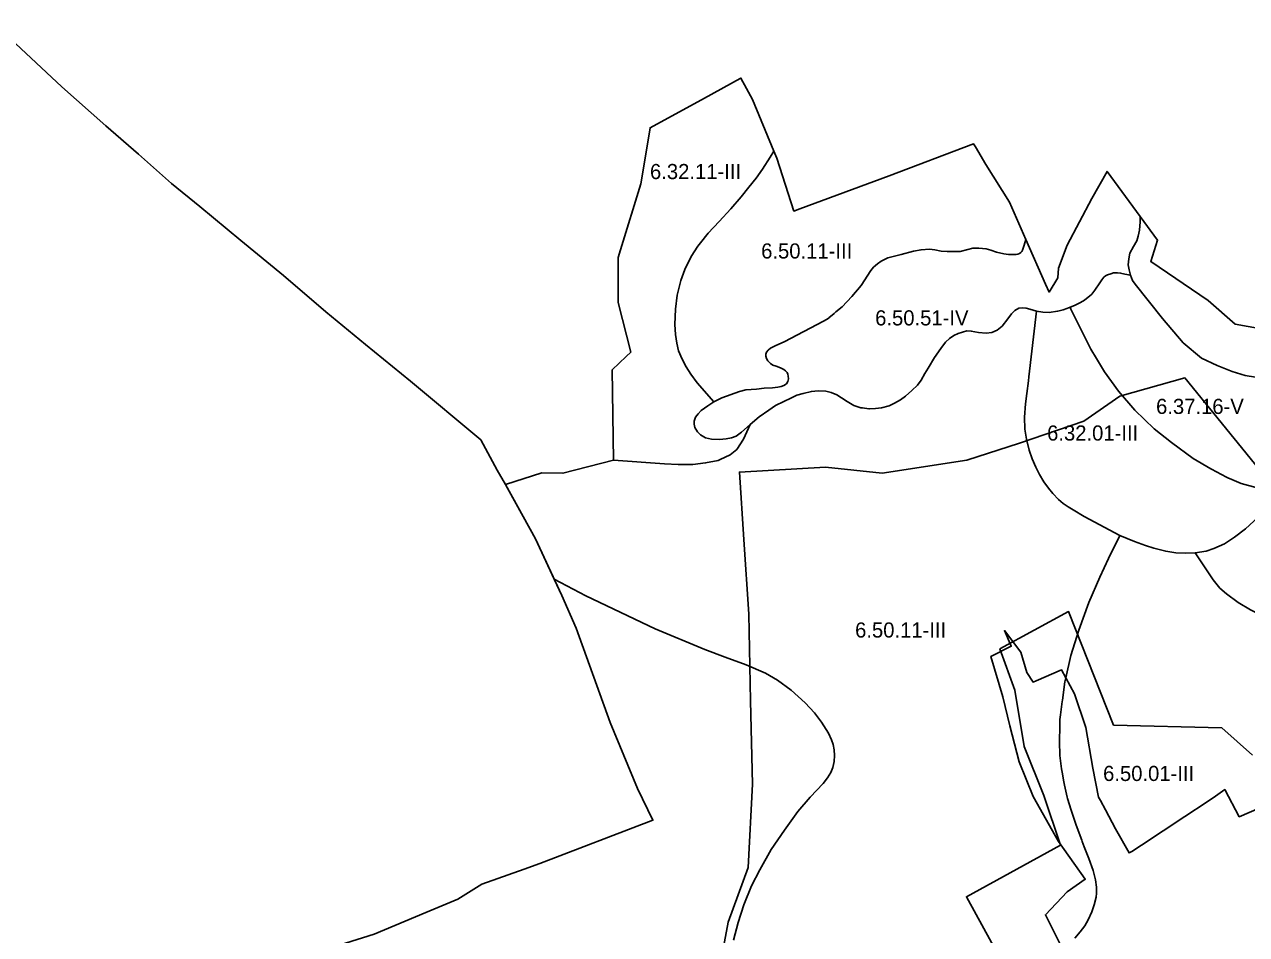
# Model space of a CAD drawing. Extents: x -555156 to -540209, y -1046851 to -1035695.
# Drawn here: x -543396 to -542589, y -1037595 to -1036993 of the extents above; entities that cross this region are included whole.
import ezdxf

# ---------------------------------------------------------------- set-up
doc = ezdxf.new("R2010")
doc.units = 0
for name, color, linetype in [('Vrstva 12', 7, 'Continuous'), ('Vrstva 27', 7, 'Continuous'), ('Vrstva 28', 7, 'Continuous'), ('Vrstva 29', 7, 'Continuous')]:
    doc.layers.add(name, color=color, linetype=linetype)

msp = doc.modelspace()

# ---------------------------------------------------------------- linework, layer by layer
at = {"layer": 'Vrstva 12'}
msp.add_lwpolyline([(-542515.82, -1037483.08), (-542593.49, -1037516.73), (-542603.09, -1037498.84), (-542609.16, -1037503.08), (-542614.79, -1037506.8), (-542629.42, -1037516.55), (-542658.02, -1037535.52), (-542664.44, -1037539.79), (-542666.3, -1037540.7), (-542675.35, -1037524.75), (-542681.98, -1037512.26), (-542685.31, -1037505.99), (-542686.48, -1037503.78), (-542690.35, -1037484.73), (-542694.88, -1037457.81), (-542702.41, -1037435.49), (-542711.03, -1037419.55), (-542727.68, -1037426.79), (-542729.77, -1037427.7), (-542733.8, -1037421.3), (-542737.96, -1037407.96), (-542748.71, -1037393.72), (-542744.2, -1037404.08), (-542757.6, -1037410.72), (-542749.7, -1037437.38), (-542745.23, -1037456.61), (-542739, -1037480.36), (-542729.66, -1037503.33), (-542713.06, -1037533.06), (-542695.314088, -1037558.028085), (-542707.15, -1037566.44), (-542721.64, -1037581.51), (-542703.165119, -1037618.59666)], dxfattribs=at)
at = {"layer": 'Vrstva 28'}
for points in [[(-543415.88, -1036992.99), (-543371.66, -1037034.13), (-543342.6, -1037060.06), (-543320.91, -1037078.65), (-543299.25, -1037098.09), (-543280.46, -1037113.29), (-543253.43, -1037135.74), (-543225.14, -1037158.87), (-543197.14, -1037182.9), (-543170.98, -1037204.56), (-543141.16, -1037228.74), (-543094.74, -1037267.62), (-543083.9, -1037287.54), (-543078.48, -1037297.12), (-543077.17, -1037299.48), (-543058.55, -1037332.92), (-543041.26, -1037370.55), (-543031.79, -1037392.1), (-543009.21, -1037454.54), (-542991.19, -1037498.05), (-542980.98, -1037519.01), (-543055.79, -1037547.74), (-543066.03, -1037551.41), (-543094.01, -1037561.29), (-543110.06, -1037571.25), (-543131.14, -1037580.09), (-543165.36, -1037594.45), (-543203.18, -1037606.26)], [(-542901.06, -1037076.86), (-542915.2, -1037042.72), (-542919.13, -1037035.39), (-542922.83, -1037028.49), (-542923.39, -1037028.8), (-542946.9, -1037041.67), (-542982.89, -1037061.33), (-542983.82, -1037066.88), (-542989.08, -1037098.45), (-543002.42, -1037141.91), (-543004.02, -1037147.14), (-543003.94, -1037176.88), (-542995.65, -1037209.54), (-542998.77, -1037212.51), (-543008.04, -1037221.32), (-543007.13, -1037280.98)], [(-542745.42, -1037110.47), (-542760.97, -1037085.53), (-542767.92, -1037073.99), (-542769.18, -1037071.9), (-542824.86, -1037092.98), (-542883.9, -1037114.88), (-542887.81, -1037116.35), (-542899.14, -1037081.5), (-542901.06, -1037076.86)], [(-542901.06, -1037076.86), (-542903.53, -1037080.78), (-542908.55, -1037088.58), (-542912.86, -1037094.71), (-542917.6, -1037100.56), (-542922.75, -1037106.97), (-542929.57, -1037114.91), (-542937.27, -1037123.3), (-542944.51, -1037130.96), (-542949.5, -1037137.28), (-542951.33, -1037139.6), (-542955.65, -1037146.43), (-542959.97, -1037155.06), (-542962.61, -1037162.17), (-542964.98, -1037171.92), (-542966.09, -1037181.11), (-542966.59, -1037191.25), (-542966.2, -1037197.93), (-542965.32, -1037203.67), (-542964.13, -1037208.76), (-542961.66, -1037214.25), (-542958.96, -1037219.43), (-542956.01, -1037224.12), (-542951.83, -1037229.9), (-542940.76, -1037242.4)], [(-542658.9, -1037119.98), (-542680.89, -1037090.17), (-542691.04, -1037108.02), (-542707.24, -1037138.98), (-542713.05, -1037154.16), (-542713.34, -1037160.45), (-542719.18, -1037169.92), (-542721.53, -1037164.59), (-542734.51, -1037135.2)], [(-542734.51, -1037135.2), (-542745.42, -1037110.47)], [(-542666.33, -1037155.28), (-542666.89, -1037151.86), (-542666.57, -1037148.03), (-542665.77, -1037144.29), (-542663.39, -1037139.68), (-542661.27, -1037135.97), (-542660.31, -1037132.87), (-542659.36, -1037128.97), (-542659.04, -1037123.48), (-542658.9, -1037119.98)], [(-542570.54, -1037195.82), (-542596.19, -1037191.22), (-542614.09, -1037175.43), (-542651.98, -1037149.77), (-542647.45, -1037135.49), (-542658.9, -1037119.98)], [(-542734.51, -1037135.2), (-542735.58, -1037138.98), (-542736.71, -1037142.23), (-542737.21, -1037143.17), (-542737.86, -1037143.84), (-542738.84, -1037144.42), (-542739.75, -1037144.81), (-542740.87, -1037145.07), (-542742.22, -1037145.17), (-542745.97, -1037145), (-542749.08, -1037144.68), (-542754.01, -1037143.56), (-542757.59, -1037142.21), (-542760.77, -1037141.41), (-542765.63, -1037140.86), (-542769.53, -1037140.86), (-542772.79, -1037141.73), (-542777.96, -1037143), (-542781.46, -1037143.16), (-542786.55, -1037143.16), (-542790.45, -1037142.77), (-542794.75, -1037141.89), (-542798.31, -1037141.65), (-542803.8, -1037141.89), (-542808.73, -1037142.92), (-542817.01, -1037144.99), (-542825.76, -1037147.3), (-542830.13, -1037149.37), (-542832.68, -1037151.2), (-542835.15, -1037153.43), (-542836.93, -1037155.65), (-542843.37, -1037165.6), (-542849.58, -1037172.85), (-542856.02, -1037179.77), (-542860.05, -1037182.96), (-542861.35, -1037183.99), (-542864.69, -1037187.02), (-542864.82, -1037187.1), (-542868.22, -1037189.18), (-542894.33, -1037202.83), (-542899.88, -1037205.19), (-542903.29, -1037207.01), (-542904.97, -1037208.33), (-542905.97, -1037209.69), (-542906.38, -1037210.97), (-542906.38, -1037212.38), (-542905.97, -1037213.79), (-542905.05, -1037215.29), (-542903.32, -1037217.23), (-542901.68, -1037218.19), (-542899.64, -1037218.87), (-542897.91, -1037219.55), (-542896.27, -1037220.23), (-542894.55, -1037221.19), (-542893.36, -1037222.01), (-542892.36, -1037223.06), (-542891.86, -1037224.28), (-542891.54, -1037225.56), (-542891.41, -1037227.29), (-542891.77, -1037229.11), (-542892.77, -1037230.47), (-542894.55, -1037231.61), (-542896.18, -1037232.29), (-542898.55, -1037232.74), (-542902.08, -1037233.22), (-542907.57, -1037233.54), (-542912.66, -1037234.09), (-542919.66, -1037234.57), (-542923.86, -1037235.55), (-542935.43, -1037239.77), (-542940.76, -1037242.4)], [(-542665.46, -1037158.78), (-542666.33, -1037155.28)], [(-542705.37, -1037179.98), (-542702.37, -1037178.75), (-542698.5, -1037176.83), (-542695.9, -1037175.33), (-542693.31, -1037173.37), (-542692.55, -1037172.65), (-542691.04, -1037171.24), (-542689.04, -1037168.6), (-542685.76, -1037163.91), (-542684.4, -1037161.82), (-542682.95, -1037160.14), (-542681.9, -1037159.18), (-542680.66, -1037158.48), (-542678.43, -1037157.76), (-542676.52, -1037157.28), (-542673.98, -1037157.12), (-542671.91, -1037157.36), (-542669.04, -1037158), (-542665.46, -1037158.78)], [(-542665.46, -1037158.78), (-542664.02, -1037162.2), (-542662.37, -1037164.63), (-542644.27, -1037187.35), (-542630.63, -1037203.37), (-542618.51, -1037213.54), (-542608.21, -1037218.42), (-542598.18, -1037222.32), (-542589.69, -1037224.96)], [(-542916.66, -1037257.37), (-542910.77, -1037252.43), (-542904.49, -1037248.01), (-542900.11, -1037244.9), (-542894.54, -1037242.28), (-542889.93, -1037240.05), (-542885.95, -1037238.06), (-542881.65, -1037236.86), (-542876.24, -1037235.59), (-542871.71, -1037235.19), (-542866.69, -1037235.43), (-542863.19, -1037236.23), (-542859.53, -1037237.74), (-542856.46, -1037239.84), (-542852.65, -1037242.31), (-542848.27, -1037244.78), (-542843.65, -1037246.37), (-542842.52, -1037246.52), (-542838.32, -1037247.09), (-542837.93, -1037247.08), (-542833.95, -1037246.93), (-542829.89, -1037246.37), (-542824.96, -1037245.02), (-542821.3, -1037243.27), (-542817.48, -1037241.2), (-542814.06, -1037238.65), (-542809.84, -1037234.99), (-542806.26, -1037231.41), (-542803.79, -1037228.06), (-542801.33, -1037223.84), (-542799.08, -1037220.2), (-542794.87, -1037213.19), (-542790.65, -1037207.14), (-542787.55, -1037202.92), (-542785.08, -1037200.53), (-542782.14, -1037198.7), (-542779.19, -1037197.27), (-542776.41, -1037196.31), (-542773.46, -1037195.6), (-542770.6, -1037195.68), (-542765.83, -1037196.63), (-542760.73, -1037197.03), (-542757.11, -1037196.6), (-542753.53, -1037195.16), (-542750.27, -1037192.54), (-542746.45, -1037187.68), (-542743.98, -1037184.34), (-542741.92, -1037182.03), (-542739.29, -1037180.59), (-542736.58, -1037180.28), (-542734.28, -1037180.59), (-542731.83, -1037181.17), (-542727.47, -1037182.53)], [(-542727.47, -1037182.53), (-542723.24, -1037183.21), (-542719.19, -1037183.35), (-542713.6, -1037182.62), (-542712.5, -1037182.36), (-542709.96, -1037181.76), (-542707.42, -1037180.78), (-542705.37, -1037179.98)], [(-542705.37, -1037179.98), (-542704.76, -1037181.21)], [(-542672.35, -1037330.88), (-542695.93, -1037318.26), (-542703.24, -1037313.95), (-542706.56, -1037311.93), (-542709.96, -1037309.58), (-542712.87, -1037307.07), (-542716.76, -1037303.02), (-542719.51, -1037299.62), (-542722.66, -1037295.24), (-542725.5, -1037290.55), (-542727.93, -1037285.61), (-542730.27, -1037280.1), (-542732.3, -1037274.43), (-542734.16, -1037267.06), (-542735.15, -1037260.48), (-542735.43, -1037252.54), (-542734.72, -1037243.76), (-542733.91, -1037236.98), (-542732.9, -1037228.58), (-542732.6, -1037226.04), (-542727.47, -1037182.53)], [(-542704.76, -1037181.21), (-542691.64, -1037207.59), (-542691.59, -1037207.69), (-542687.89, -1037213.86), (-542682.67, -1037222.57), (-542673.25, -1037235.47), (-542662.59, -1037247.87), (-542649.7, -1037260.27), (-542638.3, -1037269.44), (-542623.92, -1037279.86), (-542612.27, -1037286.81), (-542611.77, -1037287.07), (-542601.86, -1037292.26), (-542601.09, -1037292.6), (-542598.32, -1037293.8), (-542592.19, -1037296.48), (-542581.78, -1037299.21), (-542563.36, -1037300.23)], [(-542589.69, -1037224.96), (-542582.73, -1037226.08)], [(-542940.76, -1037242.4), (-542944.82, -1037245.19), (-542949.04, -1037248.29), (-542951.11, -1037250.44), (-542952.86, -1037252.59), (-542953.73, -1037255.3), (-542953.81, -1037257.13), (-542953.25, -1037259.44), (-542951.66, -1037262.3), (-542949.67, -1037264.29), (-542946.17, -1037266.28), (-542942.35, -1037267.16)], [(-542916.66, -1037257.37), (-542921.16, -1037267.12), (-542925.48, -1037273.95), (-542930.08, -1037277.57), (-542936.49, -1037280.55), (-542937.87, -1037281.19), (-542946.23, -1037282.87), (-542954.58, -1037283.98), (-542964.33, -1037283.84), (-542973.38, -1037283.42), (-543007.13, -1037280.98)], [(-542942.35, -1037267.16), (-542937.1, -1037267.4), (-542932.65, -1037267), (-542929.15, -1037266.36), (-542926.04, -1037265.09), (-542922.46, -1037262.62), (-542916.66, -1037257.37)], [(-543007.13, -1037280.98), (-543040.46, -1037289.72), (-543054.5, -1037289.35), (-543078.48, -1037297.12)], [(-543046.29, -1037359.6), (-543058.55, -1037332.92), (-543078.48, -1037297.12)], [(-542563.36, -1037300.23), (-542566.69, -1037304.01), (-542571.71, -1037309.72), (-542581.06, -1037318.8), (-542589.42, -1037326.31), (-542596.64, -1037331.83), (-542603.16, -1037336.23), (-542610.24, -1037339.49), (-542615.34, -1037341.19), (-542622.71, -1037342.18)], [(-542709.48, -1037493.62), (-542710.63, -1037487.37), (-542711.04, -1037485.12), (-542712.03, -1037476.19), (-542712.21, -1037467.08), (-542712.26, -1037464.81), (-542712.15, -1037459.14), (-542712.01, -1037452.41), (-542711.63, -1037449.35), (-542711.62, -1037449.29), (-542710.52, -1037440.51), (-542710.42, -1037439.73), (-542708.79, -1037427.61), (-542708.16, -1037424.86), (-542704.82, -1037410.25), (-542699.62, -1037393.38), (-542692.92, -1037375.03), (-542685.74, -1037358.41), (-542680.03, -1037346.01), (-542672.35, -1037330.88)], [(-542635.46, -1037342.18), (-542642.11, -1037341.19), (-542650.05, -1037339.2), (-542655.57, -1037337.5), (-542662.65, -1037334.81), (-542672.35, -1037330.88)], [(-542622.71, -1037342.18), (-542628.94, -1037342.46), (-542635.46, -1037342.18)], [(-542622.71, -1037342.18), (-542610.77, -1037360.12), (-542606.38, -1037365.54), (-542601.85, -1037369.37), (-542594.2, -1037375.04), (-542585.98, -1037379.86), (-542578.9, -1037383.4), (-542572.95, -1037385.81), (-542566.15, -1037387.94), (-542561.11, -1037388.75), (-542556.25, -1037389.23), (-542551.4, -1037389.07)], [(-543365.34, -1037661.2), (-543343.92, -1037653.2), (-543327.47, -1037647.05), (-543267.73, -1037625.19), (-543235.81, -1037616.25), (-543203.18, -1037606.26), (-543165.36, -1037594.45), (-543131.14, -1037580.09), (-543110.06, -1037571.25), (-543094.01, -1037561.29), (-543066.03, -1037551.41), (-543055.79, -1037547.74), (-542980.98, -1037519.01), (-542991.19, -1037498.05), (-543009.21, -1037454.54), (-543031.79, -1037392.1), (-543041.26, -1037370.55), (-543046.29, -1037359.6)], [(-543046.29, -1037359.6), (-543025.37, -1037370.69), (-542979.51, -1037392.52), (-542946.79, -1037406.16), (-542933.33, -1037411.16), (-542919.45, -1037416.4), (-542906.7, -1037421.93), (-542898.77, -1037426.46), (-542889.7, -1037432.98), (-542880.35, -1037441.49), (-542874.26, -1037448), (-542869.59, -1037454.24), (-542865.06, -1037461.47), (-542863.04, -1037465.81), (-542861.99, -1037468.97), (-542861.34, -1037472.45), (-542861.1, -1037476.34), (-542861.34, -1037480.31), (-542862.15, -1037484.11), (-542863.52, -1037487.6), (-542865.63, -1037490.92), (-542868.62, -1037494.72), (-542877.14, -1037503.72), (-542885.21, -1037513.36), (-542893.99, -1037525.69), (-542902.78, -1037538.3), (-542910.43, -1037551.91), (-542915.77, -1037562.35), (-542920.87, -1037574.96), (-542924.7, -1037586.72), (-542927.67, -1037598.34)], [(-542702.18, -1037597.05), (-542698.7, -1037592.84), (-542695.62, -1037588.79), (-542693.28, -1037584.83), (-542690.93, -1037579.56), (-542689.31, -1037575.03), (-542688.18, -1037570.01), (-542687.77, -1037567.2), (-542687.77, -1037563.23), (-542688.42, -1037558.54), (-542689.33, -1037554.82), (-542689.96, -1037552.22), (-542692.87, -1037544.44), (-542695.95, -1037536.59), (-542697.3, -1037533.16), (-542697.66, -1037532.19), (-542701.26, -1037522.39), (-542703.65, -1037515.01), (-542704.52, -1037512.33), (-542706.95, -1037504.65), (-542707.21, -1037503.82), (-542708.99, -1037495.84), (-542709.48, -1037493.62)]]:
    msp.add_lwpolyline(points, dxfattribs=at)
at = {"layer": 'Vrstva 29'}
for points in [[(-542580.500977, -1037286.677979), (-542629.40802, -1037226.625977), (-542672.484985, -1037238.776978), (-542696.309021, -1037255.338989), (-542738.843994, -1037269.836975), (-542773.64801, -1037281.002991), (-542829.417908, -1037289.632996), (-542866.864014, -1037285.757019), (-542923.89502, -1037288.909912), (-542921.033997, -1037333.546997), (-542917.596985, -1037382.828003), (-542916.456909, -1037440.046021), (-542915.122009, -1037495.242004), (-542918.115906, -1037550.275024), (-542931.307983, -1037586.476013), (-542941.741028, -1037641.809998)], [(-542740.791992, -1037630.138), (-542773.809021, -1037569.583008), (-542711.763, -1037535.557007), (-542722.651001, -1037502.635986), (-542735.637024, -1037470.276978), (-542741.758911, -1037432.973999), (-542751.661987, -1037405.757019), (-542706.359009, -1037381.073975), (-542676.523987, -1037456.10791), (-542605.067993, -1037457.986023), (-542584.685913, -1037476.010986)]]:
    msp.add_lwpolyline(points, dxfattribs=at)

# ---------------------------------------------------------------- texts
at = {"layer": 'Vrstva 27'}
for s, p in [('6.32.11-III', (-542982.966548, -1037095.24)), ('6.50.11-III', (-542909.496548, -1037147.73)), ('6.50.51-IV', (-542834.157241, -1037191.96)), ('6.37.16-V', (-542648.487974, -1037250.48)), ('6.32.01-III', (-542720.506548, -1037268.07)), ('6.50.11-III', (-542847.411963, -1037398.29)), ('6.50.01-III', (-542683.506548, -1037493.11))]:
    msp.add_text(s, height=10, dxfattribs=at).set_placement(p)

doc.saveas('drawing.dxf')
